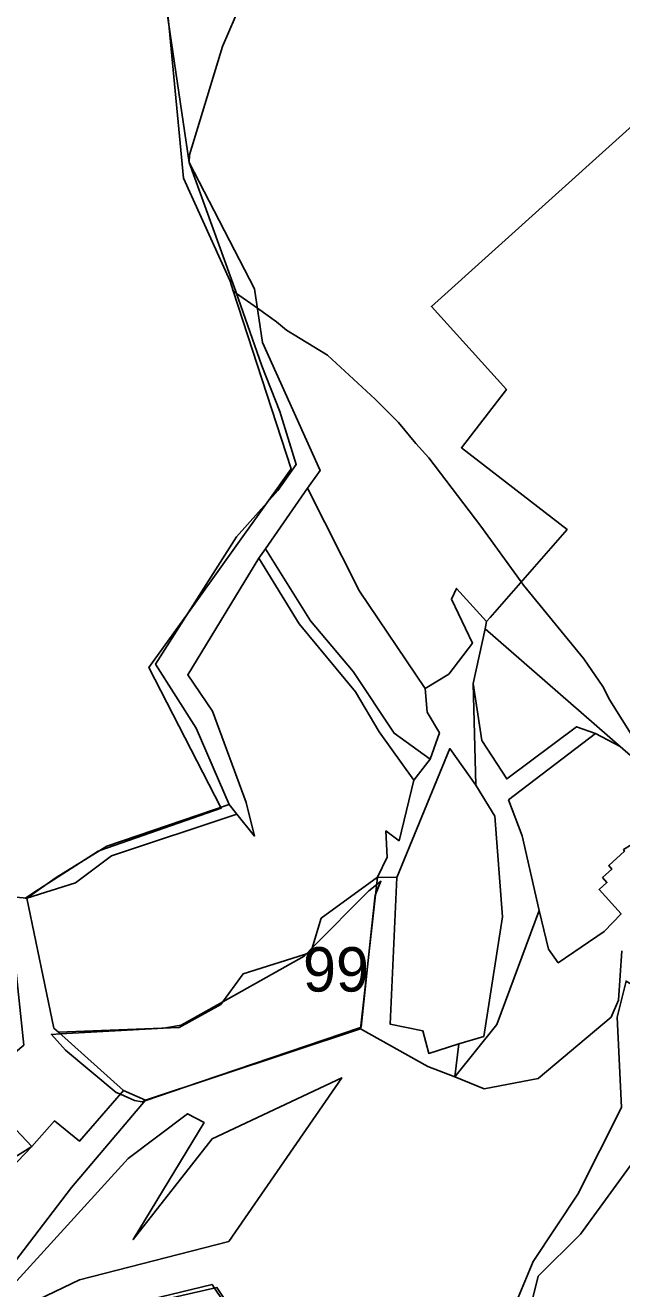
# Model space of a CAD drawing. Extents: x -477304 to -465429, y -1159113 to -1149210.
# Drawn here: x -471781.8 to -471580.1, y -1154340.7 to -1153913.5 of the extents above; entities that cross this region are included whole.
import ezdxf

# ---------------------------------------------------------------- set-up
doc = ezdxf.new("R2010")
doc.units = 0
for name, color, linetype in [('BPEJ_s', 7, 'Continuous'), ('PUPFL_s', 7, 'Continuous'), ('trav_porost_s', 7, 'Continuous')]:
    doc.layers.add(name, color=color, linetype=linetype)

msp = doc.modelspace()

# ---------------------------------------------------------------- linework, layer by layer
at = {"layer": 'BPEJ_s'}
for points in [[(-471781.79, -1154208.67), (-471781.7, -1154208.61), (-471779.17, -1154206.98), (-471775.38, -1154204.53), (-471763.04, -1154196.55), (-471757.14, -1154192.73), (-471756.56, -1154192.53), (-471715.52, -1154178.21), (-471715.65, -1154177.96), (-471739.93, -1154130.69), (-471726.58, -1154112.02), (-471700.03, -1154074.9), (-471691.91, -1154063.54), (-471696.8, -1154048.25), (-471711.51, -1154003.33), (-471712.52, -1154000), (-471728.24, -1153965.16), (-471733.12, -1153914.42), (-471733.55, -1153909.89)], [(-471571.01, -1154162.56), (-471584.18, -1154141.74), (-471586.52, -1154137.06), (-471592.89, -1154127.71), (-471613.29, -1154102.85), (-471614.1, -1154101.74), (-471627.74, -1154082.88), (-471645.37, -1154059.72), (-471649.72, -1154054.91), (-471655.57, -1154047.82), (-471663.43, -1154039.96), (-471679.58, -1154025.09), (-471693.4, -1154016.59), (-471696.8, -1154013.82), (-471703.29, -1154009.19), (-471710.32, -1154004.18), (-471711.51, -1154003.33), (-471712.52, -1154000), (-471728.24, -1153965.16), (-471733.12, -1153914.42), (-471733.55, -1153909.89)], [(-471781.79, -1154208.67), (-471781.7, -1154208.61), (-471779.17, -1154206.98), (-471775.38, -1154204.53), (-471763.04, -1154196.55), (-471757.14, -1154192.73), (-471756.56, -1154192.53), (-471715.52, -1154178.21), (-471715.65, -1154177.96), (-471739.93, -1154130.69), (-471726.58, -1154112.02), (-471700.03, -1154074.9), (-471691.91, -1154063.54), (-471696.8, -1154048.25), (-471711.51, -1154003.33)], [(-471711.51, -1154003.33), (-471710.32, -1154004.18), (-471703.29, -1154009.19), (-471696.8, -1154013.82), (-471693.4, -1154016.59), (-471679.58, -1154025.09), (-471663.43, -1154039.96), (-471655.57, -1154047.82), (-471649.72, -1154054.91), (-471645.37, -1154059.72), (-471627.74, -1154082.88), (-471614.1, -1154101.74), (-471613.29, -1154102.85), (-471592.89, -1154127.71), (-471586.52, -1154137.06), (-471584.18, -1154141.74), (-471571.01, -1154162.56)], [(-471660.24, -1154425.78), (-471717.77, -1154340.49), (-471718.62, -1154339.23), (-471764.25, -1154350.36)], [(-471660.24, -1154425.78), (-471717.77, -1154340.49), (-471718.62, -1154339.23), (-471764.25, -1154350.36)]]:
    msp.add_lwpolyline(points, dxfattribs=at)
for points in [[(-471741.3, -1154277.18), (-471742.26, -1154277.51), (-471744.82, -1154277.09), (-471749.61, -1154274.94), (-471750.98, -1154274.32), (-471768.19, -1154260.09), (-471772.93, -1154254.73), (-471769.87, -1154254.56), (-471735.04, -1154252.65), (-471734.35, -1154252.53), (-471729.09, -1154251.59), (-471714.98, -1154243.67), (-471687.44, -1154228.22), (-471686.68, -1154227.45), (-471684.83, -1154225.58), (-471665.56, -1154206.12), (-471662.96, -1154204.07), (-471661.52, -1154202.93), (-471663.34, -1154207.36), (-471663.36, -1154207.42), (-471663.43, -1154207.61), (-471664.66, -1154219.06), (-471668.2, -1154252.24), (-471668.42, -1154252.32), (-471722.5, -1154270.77)], [(-471741.3, -1154277.18), (-471722.5, -1154270.77), (-471668.42, -1154252.32), (-471668.2, -1154252.24), (-471664.66, -1154219.06), (-471663.43, -1154207.61), (-471663.36, -1154207.42), (-471663.34, -1154207.36), (-471661.52, -1154202.93), (-471662.96, -1154204.07), (-471665.56, -1154206.12), (-471684.83, -1154225.58), (-471686.68, -1154227.45), (-471687.44, -1154228.22), (-471714.98, -1154243.67), (-471729.09, -1154251.59), (-471734.35, -1154252.53), (-471735.04, -1154252.65), (-471769.87, -1154254.56), (-471772.93, -1154254.73), (-471768.19, -1154260.09), (-471750.98, -1154274.32), (-471749.61, -1154274.94), (-471744.82, -1154277.09), (-471742.26, -1154277.51)]]:
    msp.add_lwpolyline(points, close=True, dxfattribs=at)
at = {"layer": 'PUPFL_s'}
for points in [[(-471810.7, -1153760.81), (-471808.88, -1153756.06), (-471801.34, -1153768.87), (-471794.14, -1153780.14), (-471710.76, -1153910.75), (-471715.09, -1153920.74), (-471726.26, -1153957.29), (-471726.4, -1153959.93), (-471734.4, -1153905.75), (-471751.2, -1153855.14), (-471795.06, -1153815.39), (-471812.5, -1153768.05)], [(-471702.81, -1154093.72), (-471726.84, -1154133.13), (-471718.5, -1154145.46), (-471707.04, -1154176.25), (-471704.29, -1154187.63), (-471710.22, -1154180.19), (-471712.78, -1154176.98), (-471723.95, -1154151.12), (-471737.71, -1154129.54), (-471710.32, -1154086.43), (-471696.38, -1154070.81), (-471690.13, -1154061.98), (-471695.67, -1154044.05), (-471701.77, -1154028.61), (-471710.55, -1154003.53), (-471726.4, -1153959.93), (-471704.26, -1154002.66), (-471701.57, -1154020.79), (-471682.11, -1154064.01), (-471686.29, -1154070), (-471700.57, -1154090.5)], [(-471644.89, -1154161.68), (-471657, -1154152.9), (-471670.94, -1154131.96), (-471685.37, -1154114.87), (-471700.57, -1154090.5), (-471686.29, -1154070), (-471668.75, -1154104.8), (-471646.6, -1154137.81), (-471645.84, -1154145.71), (-471641.76, -1154152.79)], [(-471718.5, -1154145.46), (-471726.84, -1154133.13), (-471702.81, -1154093.72), (-471689.11, -1154115.87), (-471670.13, -1154138.86), (-471662.06, -1154152.37), (-471650.38, -1154168.79), (-471655.38, -1154189.23), (-471659.83, -1154185.93), (-471659.42, -1154194.82), (-471662.68, -1154201.56), (-471681.72, -1154215.45), (-471685.27, -1154227), (-471708.15, -1154234.24), (-471715.63, -1154244.57), (-471729.78, -1154252.35), (-471770.57, -1154253.93), (-471772.05, -1154252.6), (-471781.26, -1154208.65), (-471764.8, -1154203.41), (-471752.56, -1154194.33), (-471710.22, -1154180.19), (-471704.29, -1154187.63), (-471707.04, -1154176.25)], [(-471685.37, -1154114.87), (-471670.94, -1154131.96), (-471657, -1154152.9), (-471644.89, -1154161.68), (-471650.38, -1154168.79), (-471662.06, -1154152.37), (-471670.13, -1154138.86), (-471689.11, -1154115.87), (-471702.81, -1154093.72), (-471700.57, -1154090.5)], [(-471656.1, -1154201.69), (-471662.68, -1154201.56), (-471659.42, -1154194.82), (-471659.83, -1154185.93), (-471655.38, -1154189.23), (-471650.38, -1154168.79), (-471644.89, -1154161.68), (-471641.76, -1154152.79), (-471645.84, -1154145.71), (-471646.6, -1154137.81), (-471638.58, -1154132.89), (-471630.57, -1154122.45), (-471637.67, -1154107.51), (-471635.99, -1154103.94), (-471625.81, -1154115.13), (-471626.33, -1154117.56), (-471630.33, -1154136.07), (-471629.42, -1154170.45), (-471638.27, -1154158.06)], [(-471752.56, -1154194.33), (-471764.8, -1154203.41), (-471781.26, -1154208.65), (-471771.35, -1154201.7), (-471754.14, -1154191.03), (-471712.78, -1154176.98), (-471710.22, -1154180.19)], [(-471668.47, -1154252.77), (-471741.12, -1154276.97), (-471748.55, -1154273.72), (-471770.57, -1154253.93), (-471729.78, -1154252.35), (-471715.63, -1154244.57), (-471708.15, -1154234.24), (-471685.27, -1154227), (-471681.72, -1154215.45), (-471662.68, -1154201.56)], [(-471635.15, -1154257.95), (-471636.59, -1154269.05), (-471645.63, -1154265.51), (-471668.47, -1154252.77), (-471662.68, -1154201.56), (-471656.1, -1154201.69), (-471658.36, -1154251.29), (-471647.35, -1154253.55), (-471645.34, -1154261.16)], [(-471837.82, -1154347.78), (-471848.06, -1154350.73), (-471868.97, -1154369.01), (-471884.48, -1154408.39), (-471914.29, -1154400.4), (-471843.95, -1154310.1), (-471782.26, -1154258.3), (-471787.5, -1154208.08), (-471781.26, -1154208.65), (-471772.05, -1154252.6), (-471770.57, -1154253.93), (-471748.55, -1154273.72), (-471763.47, -1154290.85), (-471771.93, -1154283.95), (-471779.56, -1154292.63), (-471792.26, -1154279.16), (-471833.62, -1154308.86), (-471824.85, -1154317.17), (-471806.7, -1154309.59), (-471779.56, -1154292.63), (-471805.86, -1154320.16), (-471821.72, -1154319.63)], [(-471563.5, -1154271.39), (-471569.92, -1154289.14), (-471594.07, -1154322.28), (-471608.31, -1154336.4), (-471612.51, -1154353.32), (-471617.98, -1154350.44), (-471610.08, -1154331.5), (-471594.94, -1154308.77), (-471580.2, -1154279.46), (-471581.6, -1154248.83), (-471578.64, -1154236.69), (-471571.56, -1154241.01), (-471567.57, -1154246.4), (-471568.02, -1154255.01), (-471569.75, -1154256.33)], [(-471674.79, -1154269.38), (-471718.59, -1154289.97), (-471745.29, -1154324.08), (-471721.3, -1154284.54), (-471726.92, -1154281.54), (-471746.93, -1154296.63), (-471790.43, -1154344.3), (-471785.46, -1154348.33), (-471763.4, -1154337.64), (-471712.96, -1154324.74)], [(-471745.29, -1154324.08), (-471718.59, -1154289.97), (-471674.79, -1154269.38), (-471712.96, -1154324.74), (-471763.4, -1154337.64), (-471785.46, -1154348.33), (-471790.43, -1154344.3), (-471746.93, -1154296.63), (-471726.92, -1154281.54), (-471721.3, -1154284.54)], [(-471821.72, -1154319.63), (-471805.86, -1154320.16), (-471779.56, -1154292.63), (-471771.93, -1154283.95), (-471763.47, -1154290.85), (-471748.55, -1154273.72), (-471741.12, -1154276.97), (-471766.09, -1154306.48), (-471793.13, -1154341.75), (-471818.22, -1154378.77), (-471837.2, -1154392.79), (-471884.48, -1154408.39), (-471868.97, -1154369.01), (-471848.06, -1154350.73), (-471837.82, -1154347.78)], [(-471546.87, -1154421.86), (-471557.57, -1154425.07), (-471567.69, -1154431.91), (-471587.57, -1154424.46), (-471612.51, -1154353.32), (-471608.31, -1154336.4), (-471594.07, -1154322.28), (-471569.92, -1154289.14), (-471563.5, -1154271.39), (-471522.72, -1154385.84), (-471532.84, -1154381.81), (-471526.05, -1154404.53), (-471538.44, -1154412.68)], [(-471833.62, -1154308.86), (-471792.26, -1154279.16), (-471779.56, -1154292.63), (-471806.7, -1154309.59), (-471824.85, -1154317.17)], [(-471926.3, -1154475.13), (-471914.29, -1154400.4), (-471884.48, -1154408.39), (-471837.2, -1154392.79), (-471818.22, -1154378.77), (-471781.56, -1154355.08), (-471716.96, -1154340.3), (-471659.44, -1154426.99), (-471695.35, -1154463.3), (-471670.21, -1154492.33), (-471583.86, -1154490.96), (-471605.72, -1154529.05), (-471636.34, -1154591.19), (-471649.92, -1154574.53), (-471666.68, -1154549.62), (-471738.57, -1154582.21), (-471845.17, -1154603.75), (-471898.99, -1154614.43), (-471906.1, -1154578.81), (-471912.68, -1154523.9)]]:
    msp.add_lwpolyline(points, close=True, dxfattribs=at)
for points in [[(-471734.4, -1153905.75), (-471726.4, -1153959.93), (-471710.55, -1154003.53), (-471701.77, -1154028.61), (-471695.67, -1154044.05), (-471690.13, -1154061.98), (-471696.38, -1154070.81), (-471710.32, -1154086.43), (-471737.71, -1154129.54), (-471723.95, -1154151.12), (-471712.78, -1154176.98), (-471754.14, -1154191.03), (-471771.35, -1154201.7), (-471781.26, -1154208.65), (-471787.5, -1154208.08), (-471789.38, -1154191.93), (-471787.42, -1154166.99), (-471789.78, -1154146.28), (-471790.63, -1154099.78), (-471797.5, -1154043.85), (-471801.99, -1154021.33), (-471809.71, -1153954.36), (-471803.96, -1153939.59), (-471809.55, -1153887.46)], [(-471578.76, -1154463.85), (-471583.86, -1154490.96), (-471670.21, -1154492.33), (-471695.35, -1154463.3), (-471659.44, -1154426.99), (-471716.96, -1154340.3), (-471781.56, -1154355.08), (-471818.22, -1154378.77), (-471793.13, -1154341.75), (-471766.09, -1154306.48), (-471741.12, -1154276.97), (-471668.47, -1154252.77), (-471645.63, -1154265.51), (-471636.59, -1154269.05), (-471626.65, -1154273.16), (-471608.33, -1154269.66), (-471583.68, -1154248.83), (-471581.21, -1154243.16), (-471580.06, -1154226.43)], [(-471578.64, -1154236.69), (-471581.6, -1154248.83), (-471580.2, -1154279.46), (-471594.94, -1154308.77), (-471610.08, -1154331.5), (-471617.98, -1154350.44), (-471612.51, -1154353.32), (-471587.57, -1154424.46), (-471567.69, -1154431.91)]]:
    msp.add_lwpolyline(points, dxfattribs=at)
at = {"layer": 'trav_porost_s'}
msp.add_lwpolyline([(-471562.87, -1153935.14), (-471644.43, -1154008.62), (-471619.11, -1154036.72), (-471634.32, -1154056.35), (-471598.6, -1154084.01), (-471624.59, -1154113.73), (-471625.81, -1154115.13), (-471635.99, -1154103.94), (-471637.67, -1154107.51), (-471630.57, -1154122.45), (-471638.58, -1154132.89), (-471646.6, -1154137.81), (-471668.75, -1154104.8), (-471686.29, -1154070), (-471682.11, -1154064.01), (-471701.57, -1154020.79), (-471704.26, -1154002.66), (-471726.4, -1153959.93), (-471726.26, -1153957.29), (-471715.09, -1153920.74), (-471710.76, -1153910.75)], dxfattribs=at)
for points in [[(-471580.61, -1154157.35), (-471588.97, -1154152.94), (-471595.35, -1154150.7), (-471618.99, -1154168.35), (-471627.35, -1154155.3), (-471630.33, -1154136.07), (-471626.33, -1154117.56)], [(-471613.74, -1154187.52), (-471608, -1154212.82), (-471622.29, -1154251.33), (-471636.59, -1154269.05), (-471635.15, -1154257.95), (-471626.78, -1154255.38), (-471620.45, -1154214.95), (-471623.04, -1154180.87), (-471629.42, -1154170.45), (-471630.33, -1154136.07), (-471627.35, -1154155.3), (-471618.99, -1154168.35), (-471595.35, -1154150.7), (-471588.97, -1154152.94), (-471618.38, -1154175.42)], [(-471586.6, -1154201.71), (-471585.1, -1154203.35), (-471587.75, -1154205.77), (-471580.31, -1154213.92), (-471586.06, -1154219.89), (-471601.59, -1154230.46), (-471604.83, -1154225.85), (-471608, -1154212.82), (-471613.74, -1154187.52), (-471618.38, -1154175.42), (-471588.97, -1154152.94), (-471580.61, -1154157.35), (-471559.63, -1154175.62), (-471550.16, -1154182.05), (-471553.6, -1154189.65), (-471554.63, -1154188.29), (-471562.58, -1154193.54), (-471568.7, -1154190.77), (-471571.72, -1154187.46), (-471579.46, -1154192.21), (-471579.14, -1154192.74), (-471584.51, -1154197.64), (-471583.44, -1154198.82)], [(-471620.45, -1154214.95), (-471626.78, -1154255.38), (-471635.15, -1154257.95), (-471645.34, -1154261.16), (-471647.35, -1154253.55), (-471658.36, -1154251.29), (-471656.1, -1154201.69), (-471638.27, -1154158.06), (-471629.42, -1154170.45), (-471623.04, -1154180.87)]]:
    msp.add_lwpolyline(points, close=True, dxfattribs=at)

# ---------------------------------------------------------------- texts
at = {"layer": 'BPEJ_s'}
msp.add_text('99', height=15, dxfattribs=at).set_placement((-471687.87, -1154240.22))

doc.saveas('drawing.dxf')
